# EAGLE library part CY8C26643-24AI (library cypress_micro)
The CY8C25xxx/26xxx family of Programmable System-on-Chip (PSoC) microcontrollers offers a fast core, Flash program memory and SRAM data memory with configurable analog and digital peripheral blocks in a range of convinient pinouts and memory size on one single chip.
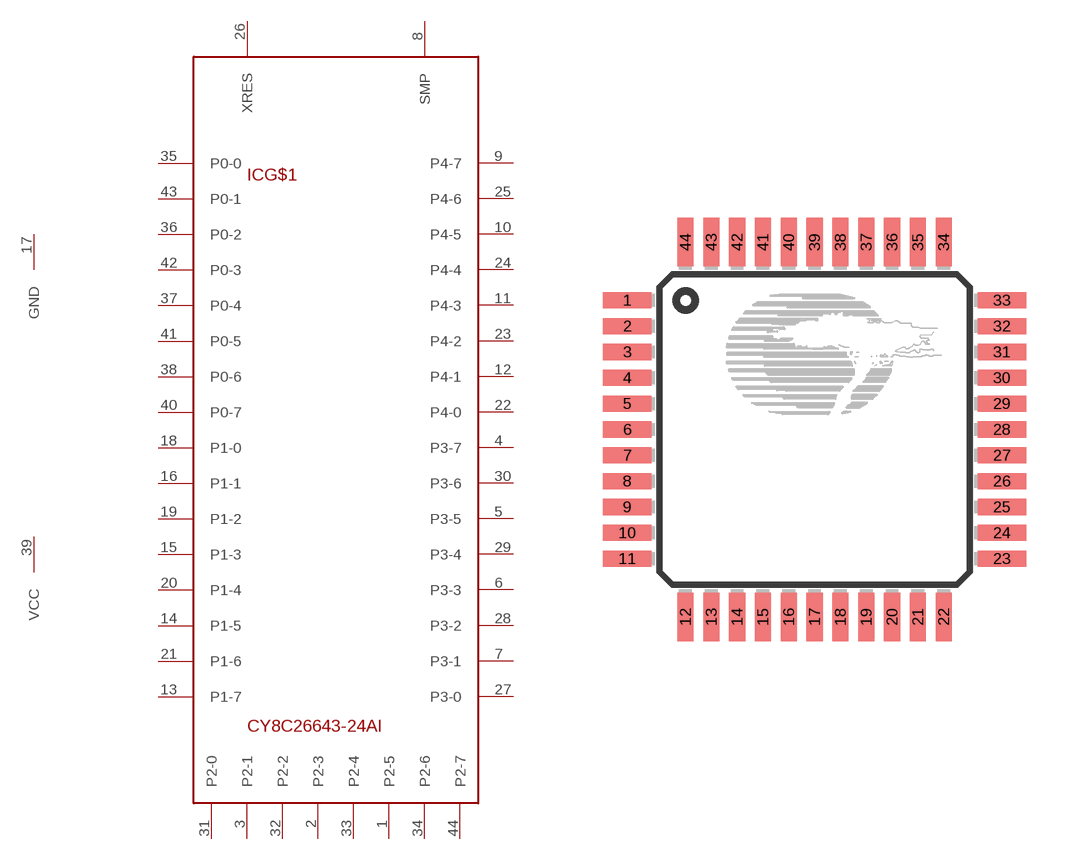
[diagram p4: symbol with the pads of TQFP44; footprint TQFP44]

Designator prefix IC; gates G$1=CY8C26643-AI G$2=GND G$3=VCC

## CY8C26643-24AI  [TQFP44]
1  G$1:P2-5
2  G$1:P2-3
3  G$1:P2-1
4  G$1:P3-7
5  G$1:P3-5
6  G$1:P3-3
7  G$1:P3-1
8  G$1:SMP  out
9  G$1:P4-7
10  G$1:P4-5
11  G$1:P4-3
12  G$1:P4-1
13  G$1:P1-7
14  G$1:P1-5
15  G$1:P1-3
16  G$1:P1-1
17  G$2:GND  pwr
18  G$1:P1-0
19  G$1:P1-2
20  G$1:P1-4
21  G$1:P1-6
22  G$1:P4-0
23  G$1:P4-2
24  G$1:P4-4
25  G$1:P4-6
26  G$1:XRES  in
27  G$1:P3-0
28  G$1:P3-2
29  G$1:P3-4
30  G$1:P3-6
31  G$1:P2-0
32  G$1:P2-2
33  G$1:P2-4
34  G$1:P2-6
35  G$1:P0-0
36  G$1:P0-2
37  G$1:P0-4
38  G$1:P0-6
39  G$3:VCC  pwr
40  G$1:P0-7
41  G$1:P0-5
42  G$1:P0-3
43  G$1:P0-1
44  G$1:P2-7

## Footprint TQFP44 (pad centres in mm)
Thin Quad Flat Package with 44 pins
smd 1.5 x 0.5: 1 -5.8,4; 2 -5.8,3.2; 3 -5.8,2.4; 4 -5.8,1.6; 5 -5.8,0.8; 6 -5.8,0; 7 -5.8,-0.8; 8 -5.8,-1.6; 9 -5.8,-2.4; 10 -5.8,-3.2; 11 -5.8,-4; 23 5.8,-4; 24 5.8,-3.2; 25 5.8,-2.4; 26 5.8,-1.6; 27 5.8,-0.8; 28 5.8,0; 29 5.8,0.8; 30 5.8,1.6; 31 5.8,2.4; 32 5.8,3.2; 33 5.8,4
smd 0.5 x 1.5: 12 -4,-5.8; 13 -3.2,-5.8; 14 -2.4,-5.8; 15 -1.6,-5.8; 16 -0.8,-5.8; 17 0,-5.8; 18 0.8,-5.8; 19 1.6,-5.8; 20 2.4,-5.8; 21 3.2,-5.8; 22 4,-5.8; 34 4,5.8; 35 3.2,5.8; 36 2.4,5.8; 37 1.6,5.8; 38 0.8,5.8; 39 0,5.8; 40 -0.8,5.8; 41 -1.6,5.8; 42 -2.4,5.8; 43 -3.2,5.8; 44 -4,5.8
